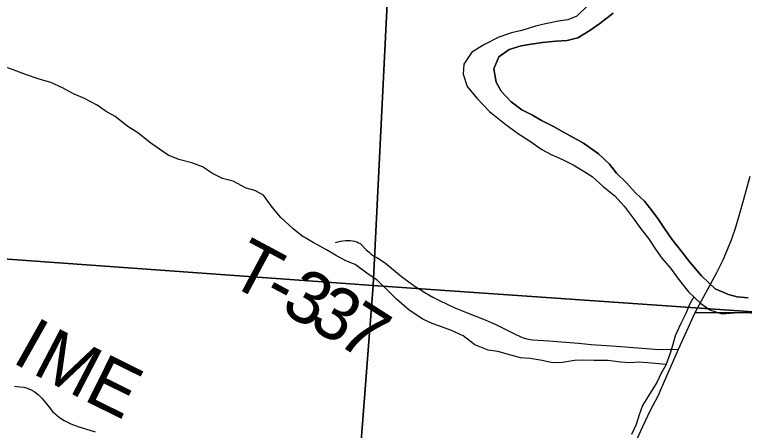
# Model space of a CAD drawing. Extents: x 0 to 34, y 0 to 22.
# Drawn here: x 7.074 to 7.868, y 17.513 to 17.965 of the extents above; entities that cross this region are included whole.
import ezdxf

# ---------------------------------------------------------------- set-up
doc = ezdxf.new("R2010")
doc.units = 0
for name, color, linetype in [('GM_X_Corporation', 7, 'Continuous'), ('GM_X_County_Road', 7, 'Continuous'), ('GM_X_County_Road_Text', 7, 'Continuous'), ('GM_X_Major_River', 7, 'Continuous'), ('GM_X_Minor_River', 7, 'Continuous'), ('GM_X_Township_Road', 7, 'Continuous'), ('GM_X_Township_Road_Text', 7, 'Continuous')]:
    doc.layers.add(name, color=color, linetype=linetype)

msp = doc.modelspace()

# ---------------------------------------------------------------- linework, layer by layer
at = {"layer": 'GM_X_Corporation'}
for points in [[(7.51615, 18.71572), (7.4643, 17.67029), (6.43864, 17.7441), (6.53912, 18.78352)], [(8.55257, 18.64968), (8.46287, 17.60104), (7.4643, 17.67029), (7.51615, 18.71572)], [(6.43864, 17.7441), (7.4643, 17.67029), (7.3858, 16.65576), (6.39117, 16.72034)], [(8.46287, 17.60104), (8.3827, 16.59195), (7.3858, 16.65576), (7.4643, 17.67029)]]:
    msp.add_lwpolyline(points, close=True, dxfattribs=at)
at = {"layer": 'GM_X_County_Road'}
for points in [[(7.80155, 17.61302), (7.81418, 17.64089), (7.8376, 17.68431), (7.84444, 17.69818), (7.84946, 17.70949), (7.85399, 17.72098), (7.85804, 17.73266), (7.8625, 17.74747), (7.86707, 17.76397), (7.87409, 17.7892)], [(7.73096, 17.45783), (7.73321, 17.46304), (7.73728, 17.47161), (7.74546, 17.49094), (7.74703, 17.49491), (7.75712, 17.517), (7.76541, 17.53394), (7.77415, 17.55083), (7.77717, 17.55773), (7.79606, 17.6009), (7.80155, 17.61302)], [(7.07436, 17.56072), (7.07993, 17.56015), (7.08441, 17.55954), (7.08816, 17.55851), (7.09234, 17.5569), (7.0956, 17.55481), (7.10007, 17.55161), (7.10414, 17.54774), (7.1076, 17.54347), (7.11187, 17.53777), (7.11574, 17.5333), (7.12327, 17.52678), (7.12815, 17.52332), (7.13557, 17.51987), (7.14437, 17.51643), (7.15629, 17.51272), (7.162, 17.51098)]]:
    msp.add_lwpolyline(points, dxfattribs=at)
at = {"layer": 'GM_X_Major_River'}
for p, q in [((7.69747, 17.97464), (7.68546, 17.96317)), ((7.68546, 17.96317), (7.67566, 17.95929)), ((7.7105, 17.95506), (7.72516, 17.96656)), ((7.65148, 17.9549), (7.64053, 17.95215)), ((7.66545, 17.95768), (7.65148, 17.9549)), ((7.67566, 17.95929), (7.66545, 17.95768)), ((7.6996, 17.94738), (7.7105, 17.95506)), ((7.61448, 17.94509), (7.6009, 17.94042)), ((7.62581, 17.94746), (7.61448, 17.94509)), ((7.64053, 17.95215), (7.62581, 17.94746)), ((7.6868, 17.93968), (7.6996, 17.94738)), ((7.6009, 17.94042), (7.58508, 17.93231)), ((7.66261, 17.93605), (7.6751, 17.93655)), ((7.6751, 17.93655), (7.6868, 17.93968)), ((7.58508, 17.93231), (7.57153, 17.92385)), ((7.61199, 17.92688), (7.6252, 17.93078)), ((7.6252, 17.93078), (7.63578, 17.93278)), ((7.63578, 17.93278), (7.64825, 17.93441)), ((7.64825, 17.93441), (7.66261, 17.93605)), ((7.57153, 17.92385), (7.56256, 17.91089)), ((7.60071, 17.91882), (7.61199, 17.92688)), ((7.59515, 17.90588), (7.60071, 17.91882)), ((7.56256, 17.91089), (7.5619, 17.89989)), ((7.59792, 17.8915), (7.59515, 17.90588)), ((7.5619, 17.89989), (7.56618, 17.88667)), ((7.60331, 17.8817), (7.59792, 17.8915)), ((7.56618, 17.88667), (7.57689, 17.87388)), ((7.614, 17.87005), (7.60331, 17.8817)), ((7.57689, 17.87388), (7.59063, 17.85961)), ((7.62581, 17.86144), (7.614, 17.87005)), ((7.59063, 17.85961), (7.60702, 17.84649)), ((7.63721, 17.85549), (7.62581, 17.86144)), ((7.6471, 17.84951), (7.63721, 17.85549)), ((7.66002, 17.84319), (7.6471, 17.84951)), ((7.60702, 17.84649), (7.62111, 17.83601)), ((7.67105, 17.83685), (7.66002, 17.84319)), ((7.62111, 17.83601), (7.63405, 17.82741)), ((7.68245, 17.83089), (7.67105, 17.83685)), ((7.63405, 17.82741), (7.64737, 17.81806)), ((7.69272, 17.82492), (7.68245, 17.83089)), ((7.64737, 17.81806), (7.65763, 17.81285)), ((7.70909, 17.81332), (7.69272, 17.82492)), ((7.65763, 17.81285), (7.66979, 17.80728)), ((7.72092, 17.80206), (7.70909, 17.81332)), ((7.66979, 17.80728), (7.68157, 17.80132)), ((7.72857, 17.79228), (7.72092, 17.80206)), ((7.68157, 17.80132), (7.6926, 17.79498)), ((7.6926, 17.79498), (7.70211, 17.78863)), ((7.70211, 17.78863), (7.71432, 17.77775)), ((7.73925, 17.78214), (7.72857, 17.79228)), ((7.74957, 17.77049), (7.73925, 17.78214)), ((7.71432, 17.77775), (7.72689, 17.76763)), ((7.7591, 17.76186), (7.74957, 17.77049)), ((7.72689, 17.76763), (7.73683, 17.75635)), ((7.73683, 17.75635), (7.74792, 17.74205)), ((7.76714, 17.7517), (7.7591, 17.76186)), ((7.77441, 17.74192), (7.76714, 17.7517)), ((7.74792, 17.74205), (7.7552, 17.73189)), ((7.7817, 17.73099), (7.77441, 17.74192)), ((7.7552, 17.73189), (7.76362, 17.72135)), ((7.78898, 17.72045), (7.7817, 17.73099)), ((7.76362, 17.72135), (7.77091, 17.70967)), ((7.79969, 17.70691), (7.78898, 17.72045)), ((7.77091, 17.70967), (7.77781, 17.69989)), ((7.80849, 17.69562), (7.79969, 17.70691)), ((7.77781, 17.69989), (7.78736, 17.68899)), ((7.82111, 17.68058), (7.80849, 17.69562)), ((7.78736, 17.68899), (7.79731, 17.67581)), ((7.79731, 17.67581), (7.80688, 17.66339)), ((7.83599, 17.66669), (7.82111, 17.68058)), ((7.85042, 17.66038), (7.83599, 17.66669)), ((7.80688, 17.66339), (7.81985, 17.65101)), ((7.8599, 17.65781), (7.85042, 17.66038)), ((7.81985, 17.65101), (7.83013, 17.6439)), ((7.87164, 17.65678), (7.8599, 17.65781)), ((7.83013, 17.6439), (7.84303, 17.63947)), ((7.84303, 17.63947), (7.85665, 17.64035)), ((7.85665, 17.64035), (7.86723, 17.64121)), ((7.86723, 17.64121), (7.87859, 17.64017))]:
    msp.add_line(p, q, dxfattribs=at)
for points in [[(7.69747, 17.97464), (7.68546, 17.96317), (7.67566, 17.95929), (7.66545, 17.95768), (7.65148, 17.9549), (7.64053, 17.95215), (7.62581, 17.94746), (7.61448, 17.94509), (7.6009, 17.94042), (7.58508, 17.93231), (7.57153, 17.92385), (7.56256, 17.91089), (7.5619, 17.89989), (7.56618, 17.88667), (7.57689, 17.87388), (7.59063, 17.85961), (7.60702, 17.84649), (7.62111, 17.83601), (7.63405, 17.82741), (7.64737, 17.81806), (7.65763, 17.81285), (7.66979, 17.80728), (7.68157, 17.80132), (7.6926, 17.79498), (7.70211, 17.78863), (7.71432, 17.77775), (7.72689, 17.76763), (7.73683, 17.75635), (7.74792, 17.74205), (7.7552, 17.73189), (7.76362, 17.72135), (7.77091, 17.70967), (7.77781, 17.69989), (7.78736, 17.68899), (7.79731, 17.67581), (7.80688, 17.66339), (7.81985, 17.65101), (7.83013, 17.6439), (7.84303, 17.63947), (7.85665, 17.64035), (7.86723, 17.64121), (7.87859, 17.64017)], [(7.72516, 17.96656), (7.7105, 17.95506), (7.6996, 17.94738), (7.6868, 17.93968), (7.6751, 17.93655), (7.66261, 17.93605), (7.64825, 17.93441), (7.63578, 17.93278), (7.6252, 17.93078), (7.61199, 17.92688), (7.60071, 17.91882), (7.59515, 17.90588), (7.59792, 17.8915), (7.60331, 17.8817), (7.614, 17.87005), (7.62581, 17.86144), (7.63721, 17.85549), (7.6471, 17.84951), (7.66002, 17.84319), (7.67105, 17.83685), (7.68245, 17.83089), (7.69272, 17.82492), (7.70909, 17.81332), (7.72092, 17.80206), (7.72857, 17.79228), (7.73925, 17.78214), (7.74957, 17.77049), (7.7591, 17.76186), (7.76714, 17.7517), (7.77441, 17.74192), (7.7817, 17.73099), (7.78898, 17.72045), (7.79969, 17.70691), (7.80849, 17.69562), (7.82111, 17.68058), (7.83599, 17.66669), (7.85042, 17.66038), (7.8599, 17.65781), (7.87164, 17.65678)]]:
    msp.add_lwpolyline(points, dxfattribs=at)
at = {"layer": 'GM_X_Minor_River'}
for p, q in [((7.0768, 17.90342), (7.06086, 17.90896)), ((7.08629, 17.89972), (7.0768, 17.90342)), ((7.09995, 17.89492), (7.08629, 17.89972)), ((7.11361, 17.89087), (7.09995, 17.89492)), ((7.12652, 17.88531), (7.11361, 17.89087)), ((7.13831, 17.87859), (7.12652, 17.88531)), ((7.15046, 17.87378), (7.13831, 17.87859)), ((7.16415, 17.86633), (7.15046, 17.87378)), ((7.17404, 17.8596), (7.16415, 17.86633)), ((7.18355, 17.854), (7.17404, 17.8596)), ((7.19765, 17.84314), (7.18355, 17.854)), ((7.2083, 17.83641), (7.19765, 17.84314)), ((7.2224, 17.82517), (7.2083, 17.83641)), ((7.23191, 17.81844), (7.2224, 17.82517)), ((7.24143, 17.81209), (7.23191, 17.81844)), ((7.25282, 17.80726), (7.24143, 17.81209)), ((7.26723, 17.8036), (7.25282, 17.80726)), ((7.27862, 17.79916), (7.26723, 17.8036)), ((7.28966, 17.79206), (7.27862, 17.79916)), ((7.3003, 17.78647), (7.28966, 17.79206)), ((7.31205, 17.78355), (7.3003, 17.78647)), ((7.32612, 17.7761), (7.31205, 17.78355)), ((7.3356, 17.77353), (7.32612, 17.7761)), ((7.3451, 17.76832), (7.3356, 17.77353)), ((7.3543, 17.75552), (7.3451, 17.76832)), ((7.36385, 17.74423), (7.3543, 17.75552)), ((7.3772, 17.73185), (7.36385, 17.74423)), ((7.38673, 17.72436), (7.3772, 17.73185)), ((7.3989, 17.71689), (7.38673, 17.72436)), ((7.41335, 17.70907), (7.3989, 17.71689)), ((7.42324, 17.70309), (7.41335, 17.70907)), ((7.43427, 17.69713), (7.42324, 17.70309)), ((7.44452, 17.69306), (7.43427, 17.69713)), ((7.45861, 17.68257), (7.44452, 17.69306)), ((7.46812, 17.67622), (7.45861, 17.68257)), ((7.47881, 17.66608), (7.46812, 17.67622)), ((7.48949, 17.65519), (7.47881, 17.66608)), ((7.50322, 17.64357), (7.48949, 17.65519)), ((7.51806, 17.63347), (7.50322, 17.64357)), ((7.52831, 17.62902), (7.51806, 17.63347)), ((7.53856, 17.62532), (7.52831, 17.62902)), ((7.54919, 17.62125), (7.53856, 17.62532)), ((7.56211, 17.61531), (7.54919, 17.62125)), ((7.57468, 17.60557), (7.56211, 17.61531)), ((7.58911, 17.60002), (7.57468, 17.60557)), ((7.59971, 17.5986), (7.58911, 17.60002)), ((7.61375, 17.59456), (7.59971, 17.5986)), ((7.62437, 17.59162), (7.61375, 17.59456)), ((7.63497, 17.59096), (7.62437, 17.59162)), ((7.64785, 17.58881), (7.63497, 17.59096)), ((7.65923, 17.58626), (7.64785, 17.58881)), ((7.68304, 17.58875), (7.66982, 17.58635)), ((7.69288, 17.58884), (7.68304, 17.58875)), ((7.70423, 17.58857), (7.69288, 17.58884)), ((7.71975, 17.58871), (7.70423, 17.58857)), ((7.733, 17.58693), (7.71975, 17.58871)), ((7.66982, 17.58635), (7.65923, 17.58626)), ((7.7436, 17.58627), (7.733, 17.58693)), ((7.75344, 17.58674), (7.7436, 17.58627)), ((7.76669, 17.58572), (7.75344, 17.58674)), ((7.78254, 17.58444), (7.76669, 17.58572))]:
    msp.add_line(p, q, dxfattribs=at)
msp.add_lwpolyline([(7.81266, 17.65788), (7.80851, 17.65015), (7.80368, 17.63911), (7.79848, 17.62883), (7.79254, 17.61552), (7.78997, 17.60602), (7.78703, 17.59652), (7.78222, 17.58359), (7.77701, 17.57407), (7.77255, 17.56456), (7.76471, 17.55198), (7.75687, 17.53978), (7.75318, 17.52952), (7.74987, 17.51888), (7.74504, 17.50822)], dxfattribs=at)
at = {"layer": 'GM_X_Township_Road'}
for points in [[(7.42335, 17.71704), (7.42586, 17.71784), (7.42847, 17.7185), (7.43107, 17.71892), (7.43434, 17.71917), (7.43715, 17.71917), (7.43956, 17.71902), (7.4418, 17.71874), (7.44383, 17.71836), (7.44635, 17.7176), (7.44839, 17.71674), (7.45005, 17.7158), (7.45152, 17.71461), (7.45669, 17.70901), (7.45968, 17.70631), (7.46152, 17.70455), (7.46338, 17.70319), (7.46566, 17.70181), (7.46798, 17.70062), (7.46983, 17.69957), (7.47173, 17.69839), (7.47363, 17.69719), (7.47553, 17.69591), (7.47743, 17.69454), (7.4796, 17.69279), (7.4949, 17.67989), (7.50294, 17.67434), (7.50972, 17.66907), (7.51527, 17.66575), (7.52044, 17.66243), (7.52917, 17.65755), (7.53624, 17.65394), (7.55303, 17.64606), (7.56544, 17.64102), (7.5858, 17.6328), (7.58909, 17.63147), (7.59245, 17.63008), (7.59693, 17.62799), (7.61784, 17.61768), (7.62543, 17.61408), (7.62729, 17.61338), (7.63103, 17.61218), (7.63305, 17.61174), (7.63501, 17.61136), (7.6376, 17.6111), (7.65502, 17.61019), (7.68748, 17.60756), (7.70101, 17.6062), (7.72876, 17.60411), (7.77498, 17.60068), (7.79606, 17.6009)], [(7.81418, 17.64089), (7.84815, 17.64091), (7.88622, 17.64091)]]:
    msp.add_lwpolyline(points, dxfattribs=at)

# ---------------------------------------------------------------- texts
at = {"layer": 'GM_X_County_Road_Text'}
for s, rotation, p in [('I', 330.64126, (7.07004, 17.58764)), ('M', 332.52518, (7.09214, 17.57524)), ('E', 333.65462, (7.14794, 17.54625))]:
    msp.add_text(s, height=0.05682, rotation=rotation, dxfattribs=at).set_placement(p)
at = {"layer": 'GM_X_Township_Road_Text'}
for s, rotation, p in [('T', 331.83625, (7.30416, 17.67335)), ('3', 331.31187, (7.36205, 17.6423)), ('-', 331.71722, (7.3416, 17.6533)), ('3', 329.82073, (7.39241, 17.62569)), ('7', 327.46176, (7.42214, 17.60842))]:
    msp.add_text(s, height=0.05682, rotation=rotation, dxfattribs=at).set_placement(p)

doc.saveas('drawing.dxf')
